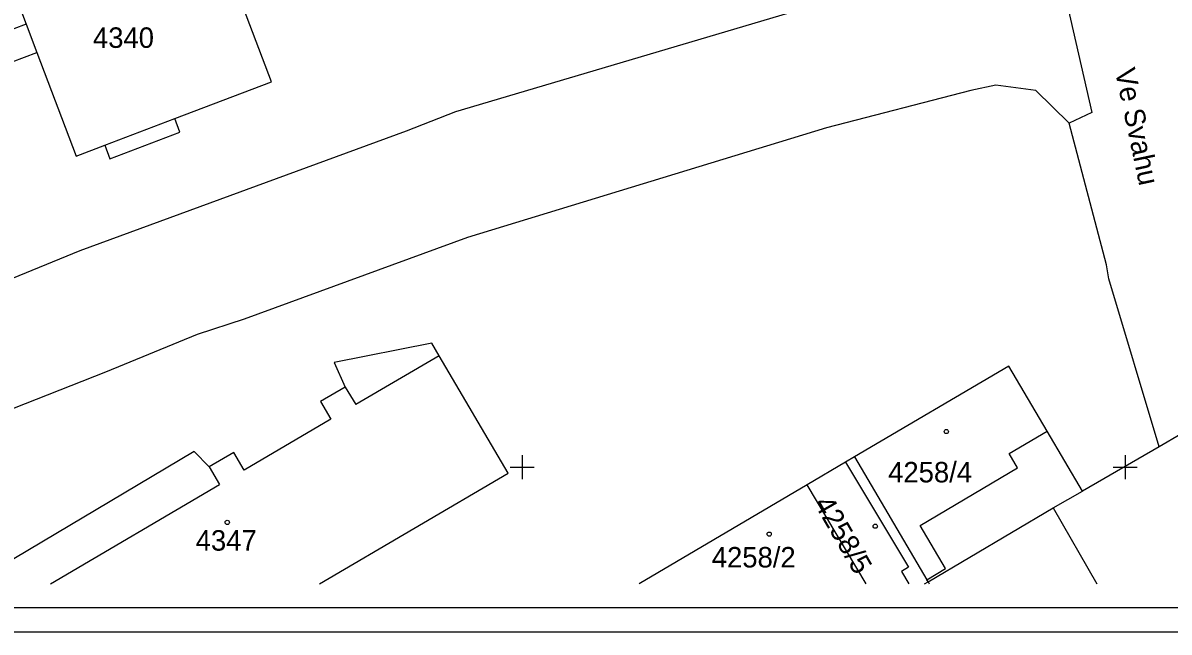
# Model space of a CAD drawing. Extents: x -771260 to -770828, y -1053564 to -1052811.
# Drawn here: x -771091.4 to -770996.4, y -1053563.7 to -1053513.1 of the extents above; entities that cross this region are included whole.
import ezdxf

# ---------------------------------------------------------------- set-up
doc = ezdxf.new("R2010")
doc.units = 0
for name, color, linetype in [('14_8_2023_krizky', 7, 'Continuous'), ('25_3_2019_krizky_JTSK', 7, 'Continuous'), ('25_3_2019_ram_ggs', 7, 'Continuous'), ('DKM_Hranice parcel', 7, 'Continuous'), ('DKM_Parcelní čísla', 7, 'Continuous'), ('DKM_Pop  PČ popisy', 7, 'Continuous'), ('DKM_Vnitřní kresba', 7, 'Continuous'), ('DKM_Značky budov', 7, 'Continuous')]:
    doc.layers.add(name, color=color, linetype=linetype)

# ---------------------------------------------------------------- blocks, each defined once
blk = doc.blocks.new('KRIZEK')
at = {"layer": '25_3_2019_krizky_JTSK'}
for p, q in [((0, 10), (0, -10)), ((-10, 0), (10, 0))]:
    blk.add_line(p, q, dxfattribs=at)

msp = doc.modelspace()

# ---------------------------------------------------------------- linework, layer by layer
at = {"layer": '25_3_2019_ram_ggs'}
for points in [[(-771251.022, -1053563.673), (-771251.022, -1052969.173), (-770830.522, -1052969.173), (-770830.522, -1053563.673)], [(-771249.022, -1053561.673), (-771249.022, -1052971.173), (-770832.522, -1052971.173), (-770832.522, -1053561.673)]]:
    msp.add_lwpolyline(points, close=True, dxfattribs=at)
at = {"layer": 'DKM_Hranice parcel'}
for p, q in [((-771023.19, -1053549.59), (-771026.38, -1053551.47)), ((-771021.487, -1053559.673), (-771026.38, -1053551.47)), ((-771016.646, -1053559.673), (-771016.35, -1053559.5)), ((-771016.35, -1053559.5), (-771016.249, -1053559.673))]:
    msp.add_line(p, q, dxfattribs=at)
for points in [[(-771147.894, -1053559.673), (-771133.84, -1053552.45), (-771127.49, -1053549.47), (-771118.2, -1053544.86), (-771110.56, -1053541.46), (-771109.13, -1053540.98), (-771100.69, -1053537.62), (-771093.44, -1053534.79), (-771086.66, -1053532.03), (-771059.61, -1053522.09), (-771055.5, -1053520.5), (-771027.24, -1053512.13), (-771009.32, -1053507.34), (-771007.58, -1053503.69), (-771007.32, -1053500.59)], [(-771081.02, -1053502.27), (-771085.36, -1053503.96), (-771085.8, -1053502.84), (-771091.57, -1053505.08), (-771091.14, -1053506.2), (-771093.47, -1053507.1), (-771091.13, -1053513.26), (-771093.19, -1053514.04), (-771092.3, -1053516.38), (-771090.25, -1053515.6), (-771086.99, -1053524.19), (-771084.62, -1053523.29), (-771084.2, -1053524.41), (-771078.39, -1053522.22), (-771078.82, -1053521.09), (-771070.78, -1053518.03), (-771077.31, -1053500.83)], [(-771007.32, -1053500.59), (-771002.78, -1053520.59), (-771004.65, -1053521.45)], [(-771004.65, -1053521.45), (-771007.41, -1053518.76), (-771010.74, -1053518.32), (-771012.8, -1053518.76), (-771024.78, -1053521.85), (-771054.54, -1053530.96), (-771073.06, -1053537.71), (-771076.96, -1053539), (-771084.56, -1053542.11), (-771096.08, -1053546.64), (-771112.85, -1053553.75), (-771115.55, -1053555.02), (-771125.81, -1053559.673)], [(-770997.2, -1053548.3), (-771001.35, -1053534.38), (-771001.56, -1053533.21), (-771004.65, -1053521.45)], [(-771066.799, -1053559.673), (-771051.18, -1053550.48), (-771056.9, -1053540.75), (-771057.51, -1053539.71), (-771065.6, -1053541.3), (-771064.67, -1053543.35), (-771066.74, -1053544.56), (-771065.88, -1053546.02)], [(-771006.48, -1053547), (-771009.66, -1053541.62), (-771022.44, -1053549.15), (-771023.19, -1053549.59)], [(-771065.88, -1053546.02), (-771073.05, -1053550.24), (-771073.91, -1053548.77), (-771075.96, -1053549.98), (-771077.21, -1053548.69), (-771095.663, -1053559.673)], [(-771016.35, -1053559.5), (-771016.45, -1053559.33), (-771014.9, -1053558.41), (-771017.01, -1053554.84), (-771008.92, -1053550.06), (-771009.63, -1053548.86), (-771006.48, -1053547)], [(-770997.2, -1053548.3), (-771003.55, -1053551.98), (-771006.48, -1053547)], [(-770990.515, -1053559.673), (-770992.75, -1053554.72), (-770995.4, -1053547.25), (-770997.2, -1053548.3)], [(-771023.19, -1053549.59), (-771017.97, -1053558.29), (-771018.56, -1053558.64), (-771017.953, -1053559.673)], [(-771026.38, -1053551.47), (-771040.309, -1053559.673)]]:
    msp.add_lwpolyline(points, dxfattribs=at)
at = {"layer": 'DKM_Vnitřní kresba'}
for p, q in [((-771091.13, -1053513.26), (-771090.25, -1053515.6)), ((-771084.62, -1053523.29), (-771078.82, -1053521.09)), ((-771056.9, -1053540.75), (-771063.81, -1053544.81)), ((-771064.67, -1053543.35), (-771063.81, -1053544.81)), ((-771022.44, -1053549.15), (-771016.45, -1053559.33)), ((-771075.96, -1053549.98), (-771075.1, -1053551.44)), ((-771089.117, -1053559.673), (-771075.1, -1053551.44)), ((-771005.98, -1053553.38), (-771003.55, -1053551.98)), ((-771016.35, -1053559.5), (-771005.98, -1053553.38)), ((-771005.98, -1053553.38), (-771002.351, -1053559.673))]:
    msp.add_line(p, q, dxfattribs=at)
at = {"layer": 'DKM_Značky budov'}
for centre in [(-771014.837, -1053547.039), (-771074.46, -1053554.577), (-771029.523, -1053555.548), (-771020.727, -1053554.889)]:
    msp.add_circle(centre, 0.175, dxfattribs=at)

# ---------------------------------------------------------------- block references
at = {"layer": '14_8_2023_krizky', "xscale": 0.1, "yscale": 0.10000000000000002}
for p in [(-771050, -1053550), (-771000, -1053550)]:
    msp.add_blockref('KRIZEK', p, dxfattribs=at)

# ---------------------------------------------------------------- texts
at = {"layer": 'DKM_Parcelní čísla'}
for s, p in [('4340', (-771085.594, -1053515.22)), ('4258/4', (-771019.657, -1053551.259)), ('4347', (-771077.076, -1053556.919)), ('4258/2', (-771034.282, -1053558.315))]:
    msp.add_text(s, height=1.7, dxfattribs=at).set_placement(p)
msp.add_text('4258/5', height=1.7, rotation=300, dxfattribs=at).set_placement((-771025.849, -1053553.006))
at = {"layer": 'DKM_Pop  PČ popisy'}
msp.add_text('Ve Svahu', height=1.7, rotation=282, dxfattribs=at).set_placement((-771000.871, -1053517.099))

doc.saveas('drawing.dxf')
